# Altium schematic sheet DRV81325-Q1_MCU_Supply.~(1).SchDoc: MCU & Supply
size 431 x 279 mm; Date: Not shown in title block; ApprovedBy: Not shown in title block; CheckedBy: Not shown in title block; Author: Not shown in title block; CompanyName: Not shown in title block; DrawnBy: Mojtaba Afshar; Engineer: Not shown in title block; Organization: Not shown in title block; Address1: Not shown in title block; Address2: Not shown in title block; Address3: Not shown in title block; Address4: Not shown in title block; DocumentNumber: 2; Revision: Use project parameter SCH_Rev; SheetNumber: 1; SheetTotal: 5; PageSetup: Record=PageOptions¦CenterHorizontal=True¦CenterVertical=True¦PrintScale=1.00¦XCorrection=1.00¦YCorrection=1.00¦PrintKind=0¦BorderSize=5000000¦LeftOffset=0¦BottomOffset=0¦Orientation=2¦PaperLength=1000¦PaperWidth=1000¦Scale=100¦PaperSource=15¦PrintQuality=600¦MediaType=1¦DitherType=10¦PaperKind=Letter¦PrintScaleMode=1
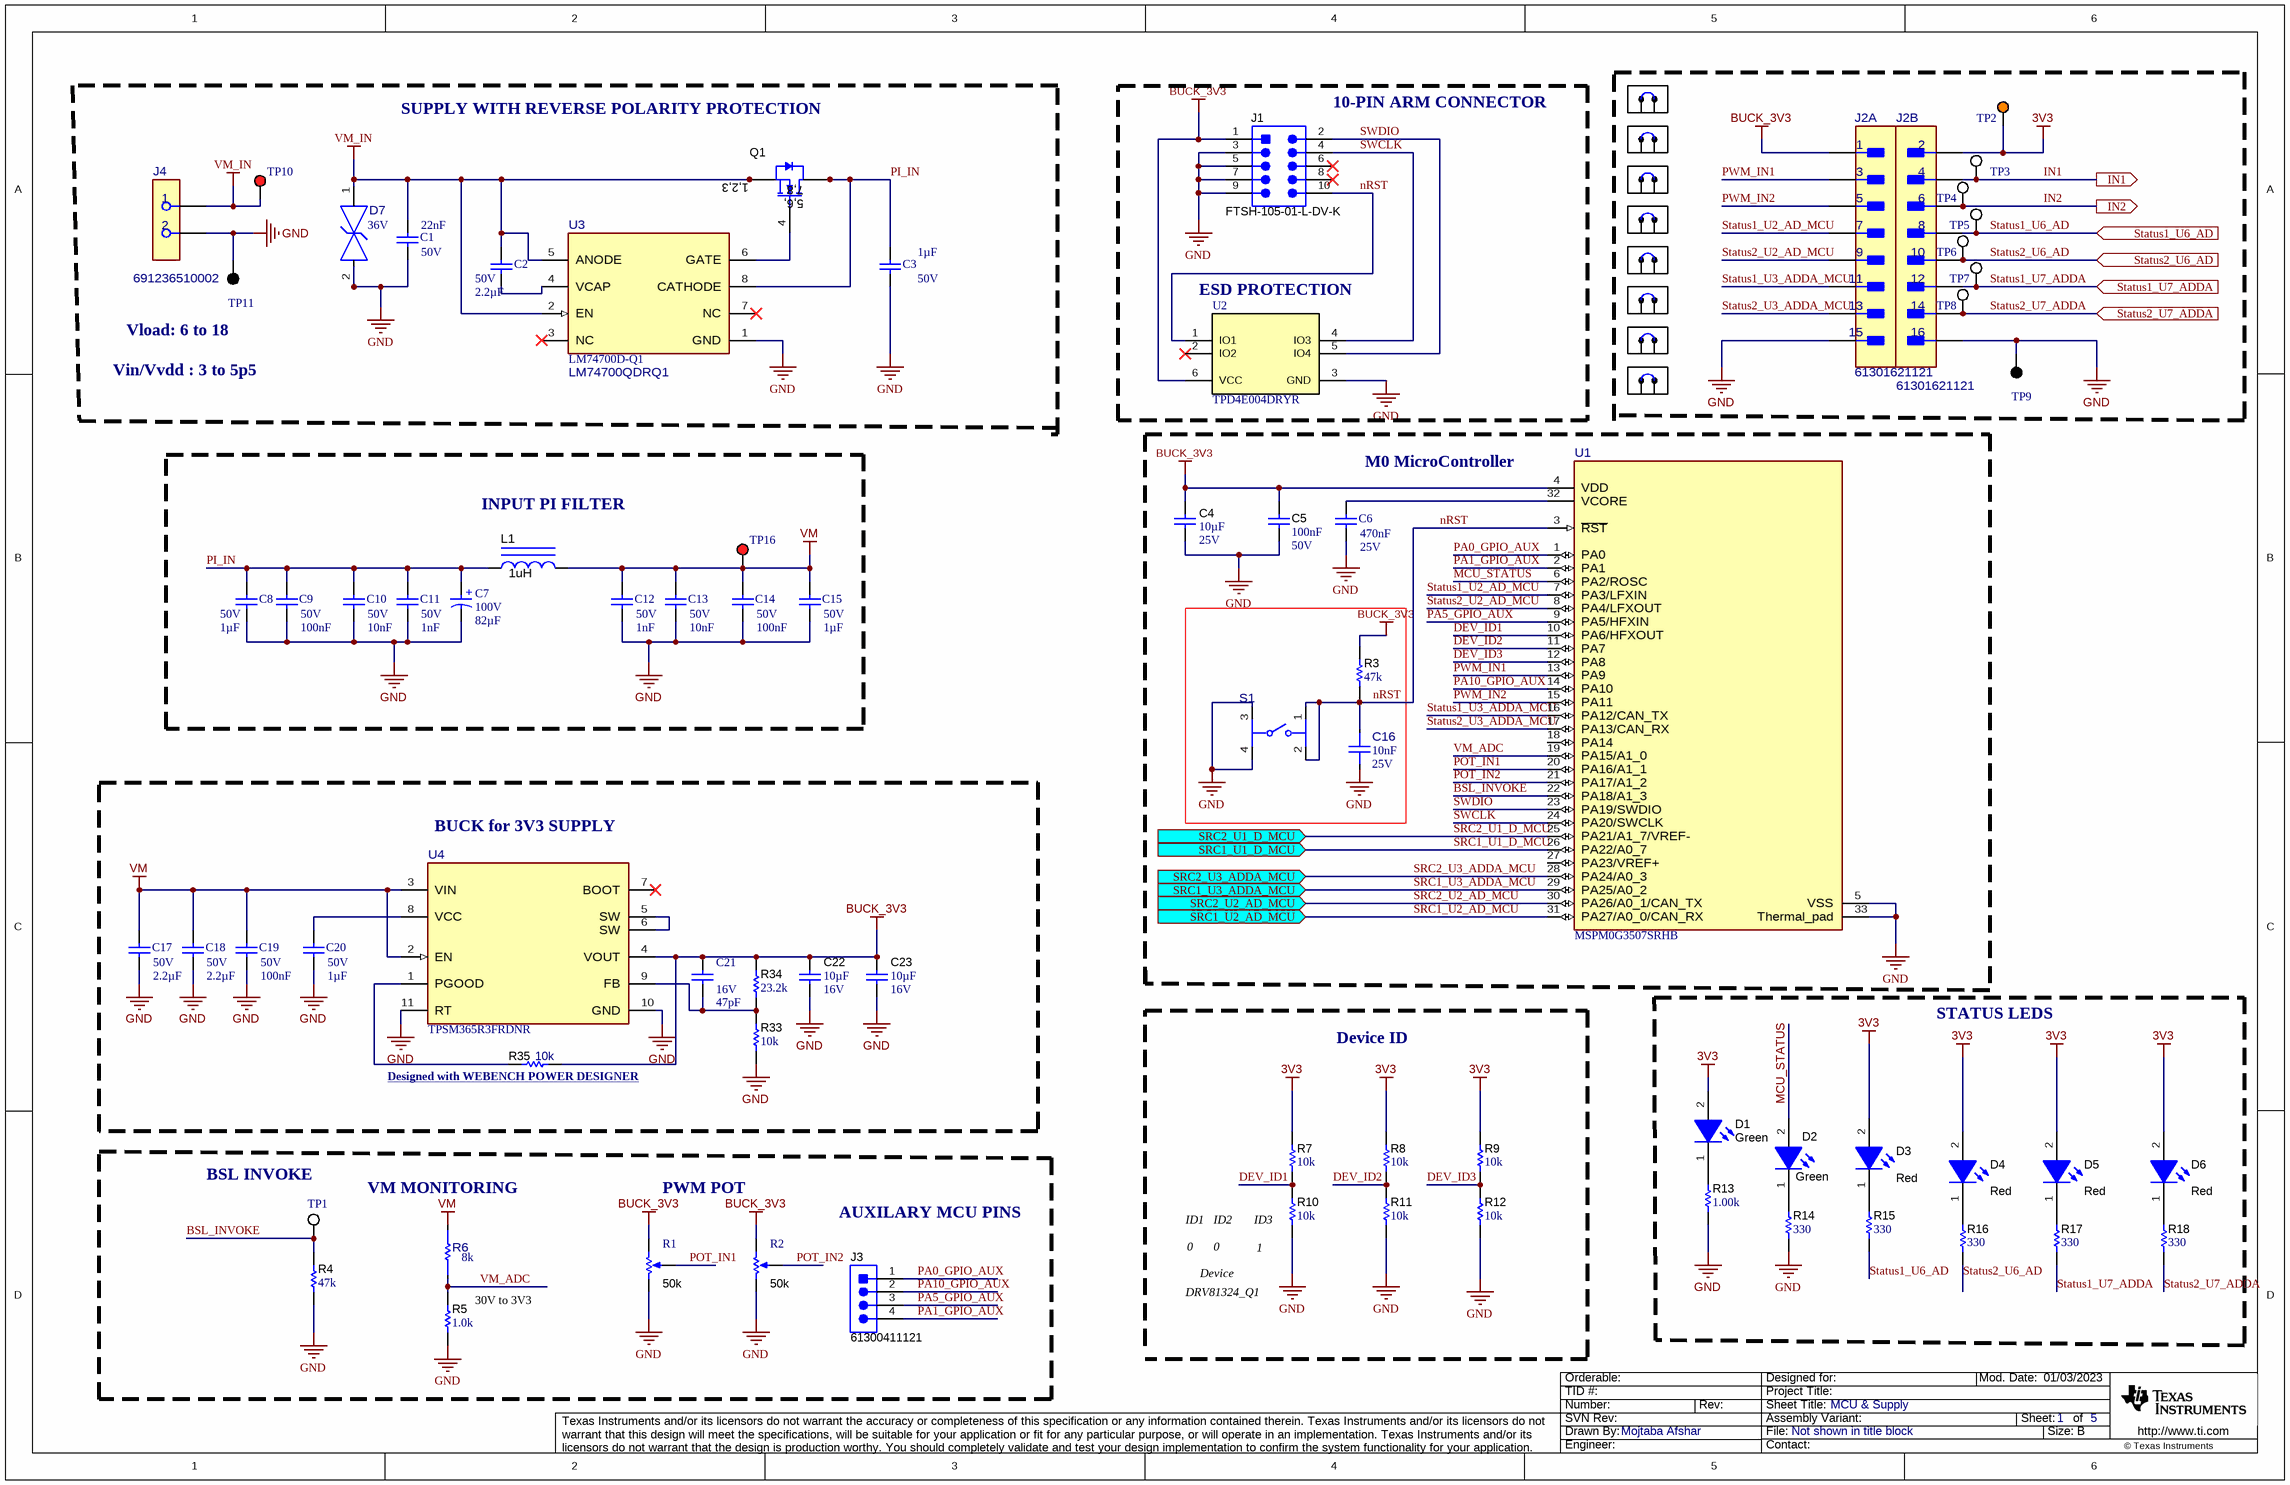
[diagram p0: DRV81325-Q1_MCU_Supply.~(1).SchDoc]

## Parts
C1  Cap_F: 22nF  Rated Voltage (DC): 50V  [WCAP-CSGP_0603_L1.6W0.8H0.8_Reflow]  (hidden comment: 885012206091)
C2  Cap_F: 2.2µF  Rated Voltage (DC): 50V  [WCAP-CSGP_1812_L4.5W3.2H2.5]  (hidden comment: 885012210032)
C3  Cap_F: 1µF  Rated Voltage (DC): 50V  [WCAP-CSGP_1206_L3.2W1.6H1.6]  (hidden comment: 885012208093)
C4  Cap_F: 10µF  VDC_V: 25V  [0603]  (hidden comment: GRM188R61E106KA73D)
C5  Cap_F: 100nF  VDC_V: 50V  [0603]  (hidden comment: 885012206095)
C6  value 470nF  Rated Voltage (DC): 25V  [WCAP-CSGP_0603_L1.6W0.8H0.8_Reflow]  (hidden comment: 885012206075R)
C7  Cap_F: 82µF  Rated Voltage (DC): 100V  [WCAP-ATUL_D10H20]  (hidden comment: 860040875004)
C8  Cap_F: 1µF  Rated Voltage (DC): 50V  [WCAP-CSGP_1206_L3.2W1.6H1.6]  (hidden comment: 885012208093)
C9  Cap_F: 100nF  Rated Voltage (DC): 50V  [WCAP-CSGP_0603_L1.6W0.8H0.8_Reflow]  (hidden comment: 885012206095)
C10  Cap_F: 10nF  Rated Voltage (DC): 50V  [WCAP-CSGP_0402_L1W0.5H0.5]  (hidden comment: 885012205067)
C11  Cap_F: 1nF  Rated Voltage (DC): 50V  [WCAP-CSGP_0402_L1W0.5H0.5]  (hidden comment: 885012205061)
C12  Cap_F: 1nF  Rated Voltage (DC): 50V  [WCAP-CSGP_0402_L1W0.5H0.5]  (hidden comment: 885012205061)
C13  Cap_F: 10nF  Rated Voltage (DC): 50V  [WCAP-CSGP_0402_L1W0.5H0.5]  (hidden comment: 885012205067)
C14  Cap_F: 100nF  Rated Voltage (DC): 50V  [WCAP-CSGP_0603_L1.6W0.8H0.8_Reflow]  (hidden comment: 885012206095)
C15  Cap_F: 1µF  Rated Voltage (DC): 50V  [WCAP-CSGP_1206_L3.2W1.6H1.6]  (hidden comment: 885012208093)
C16  Cap_F: 10nF  VDC_V: 25V  [FP-885012206065_0603-MFG]  (hidden comment: 885012206065)
C17  Cap_F: 2.2µF  Rated Voltage (DC): 50V  [WCAP-CSGP_1812_L4.5W3.2H2.5]  (hidden comment: 885012210032)
C18  Cap_F: 2.2µF  Rated Voltage (DC): 50V  [WCAP-CSGP_1812_L4.5W3.2H2.5]  (hidden comment: 885012210032)
C19  Cap_F: 100nF  Rated Voltage (DC): 50V  [WCAP-CSGP_0603_L1.6W0.8H0.8_Reflow]  (hidden comment: 885012206095)
C20  Cap_F: 1µF  Rated Voltage (DC): 50V  [WCAP-CSGP_1206_L3.2W1.6H1.6]  (hidden comment: 885012208093)
C21  Rated Voltage (DC): 16V  Cap_F: 47pF  [WCAP-CSGP_0402_L1W0.5H0.5]  (hidden comment: 885012005029)
C22  VDC_V: 16V  ValueDisplayed: 10µF  [0805_150]  (hidden comment: 885012107014)
C23  VDC_V: 16V  ValueDisplayed: 10µF  [0805_150]  (hidden comment: 885012107014)
D1  value Green  [WL-SMCW_GREEN]  (hidden comment: 150060VS75000)
D2  value Green  [WL-SMCW_GREEN]  (hidden comment: 150060VS75000)
D3  value Red  [WL-SMCW_RED]  (hidden comment: 150060RS75000)
D4  value Red  [WL-SMCW_RED]  (hidden comment: 150060RS75000)
D5  value Red  [WL-SMCW_RED]  (hidden comment: 150060RS75000)
D6  value Red  [WL-SMCW_RED]  (hidden comment: 150060RS75000)
D7  VRWM: 36V  [FP-SMBJ36CA-13-F_SMB-MFG]  (hidden comment: SMBJ36CA-13-F)
J1  FTSH-105-01-L-DV-K  [Samtec_FTSH-105-01-x-DV-K]
J2  61301621121  [FP-61301621121_HDR16-MFG]  (parts A,B of 2)
J3  61300411121  [WURTH_61300411121]
J4  691236510002  [FP-691236510002_HHR2-MFG]
L1  ValueDisplayed: 1uH  [WE-HCC_1210]  (hidden comment: 7443320100)
Q1  CSD19502Q5B  [DNK0008A]  (value not drawn)
R1  value 50k  [Bourns_3352T]  (hidden comment: 3352T-1-503LF)
R2  value 50k  [Bourns_3352T]  (hidden comment: 3352T-1-503LF)
R3  ValueDisplayed: 47k  [0402]  (hidden comment: CRCW040247K0JNED)
R4  ValueDisplayed: 47k  [0402]  (hidden comment: CRCW040247K0JNED)
R5  ValueDisplayed: 1.0k  [0603]  (hidden comment: RC0603JR-071KL)
R6  value 8k  [FP-RT0603BRE078KL_0603-MFG]  (hidden comment: RT0603BRE078KL)
R7  ValueDisplayed: 10k  [0603L]  (hidden comment: RC0603JR-0710KL)
R8  ValueDisplayed: 10k  [0603L]  (hidden comment: RC0603JR-0710KL)
R9  ValueDisplayed: 10k  [0603L]  (hidden comment: RC0603JR-0710KL)
R10  ValueDisplayed: 10k  [0603L]  (hidden comment: RC0603JR-0710KL)
R11  ValueDisplayed: 10k  [0603L]  (hidden comment: RC0603JR-0710KL)
R12  ValueDisplayed: 10k  [0603L]  (hidden comment: RC0603JR-0710KL)
R13  ValueDisplayed: 1.00k  [0603]  (hidden comment: RC0603FR-071KL)
R14  ValueDisplayed: 330  [0603]  (hidden comment: RC0603JR-07330RL)
R15  ValueDisplayed: 330  [0603]  (hidden comment: RC0603JR-07330RL)
R16  ValueDisplayed: 330  [0603]  (hidden comment: RC0603JR-07330RL)
R17  ValueDisplayed: 330  [0603]  (hidden comment: RC0603JR-07330RL)
R18  ValueDisplayed: 330  [0603]  (hidden comment: RC0603JR-07330RL)
R33  ValueDisplayed: 10k  [0603L]  (hidden comment: RC0603JR-0710KL)
R34  ValueDisplayed: 23.2k  [0603]  (hidden comment: RC0603FR-0723K2L)
R35  ValueDisplayed: 10k  [0603L]  (hidden comment: RC0603JR-0710KL)
S1  430481025816  [FP-430481025816_SMT_SW_6MM2_6MM2-MFG]  (value not drawn)
SH1-J2-1  60900213421  [Wurth_60900213421]  (value not drawn)
SH2-J2  60900213421  [Wurth_60900213421]  (value not drawn)
SH3-J2  60900213421  [Wurth_60900213421]  (value not drawn)
SH4-J2  60900213421  [Wurth_60900213421]  (value not drawn)
SH5-J2  60900213421  [Wurth_60900213421]  (value not drawn)
SH6-J2  60900213421  [Wurth_60900213421]  (value not drawn)
SH7-J2  60900213421  [Wurth_60900213421]  (value not drawn)
SH8-J2  60900213421  [Wurth_60900213421]  (value not drawn)
TP1  5002  [Keystone5002]  (value not drawn)
TP2  5013  [Keystone5013]  (value not drawn)
TP3  5012  [Keystone5012]  (value not drawn)
TP4  5012  [Keystone5012]  (value not drawn)
TP5  5012  [Keystone5012]  (value not drawn)
TP6  5012  [Keystone5012]  (value not drawn)
TP7  5012  [Keystone5012]  (value not drawn)
TP8  5012  [Keystone5012]  (value not drawn)
TP9  5011  [Keystone5011]  (value not drawn)
TP10  5010  [Keystone5010]  (value not drawn)
TP11  5011  [Keystone5011]  (value not drawn)
TP16  5010  [Keystone5010]  (value not drawn)
U1  MSPM0G3507SRHB  [RHB0032E-MFG]
U2  TPD4E004DRYR  [DRY0006A]
U3  LM74700QDRQ1  PartNumber: LM74700D-Q1  [D0008A-MFG]
U4  TPSM365R3FRDNR  [RDN0011A-MFG]

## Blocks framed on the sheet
INPUT PI FILTER: C7-C15 L1 TP16
BUCK for 3V3 SUPPLY: C17-C23 R33-R35 U4
STATUS LEDS: D1-D6 R13-R18

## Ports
IN1 (out), IN2 (out), SRC1_U1_D_MCU (in), SRC1_U2_AD_MCU (in), SRC1_U3_ADDA_MCU (in), SRC2_U1_D_MCU (in), SRC2_U2_AD_MCU (in), SRC2_U3_ADDA_MCU (in), Status1_U6_AD (in), Status1_U7_ADDA (in), Status2_U6_AD (in), Status2_U7_ADDA (in)

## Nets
3V3: D1.2(A) D3.2(A) D4.2(A) D5.2(A) D6.2(A) J2.2 R7.1 R8.1 R9.1 TP2.1
BUCK_3V3: C4.1 C5.1 C21.2 C22.1 C23.1 J1.1 J2.1 R1.1(CCW) R2.1(CCW) R3.2 R34.2 R35.2 U1.4(VDD) U2.6(VCC) U4.4(VOUT)
GND: C1.1 C3.1 C4.2 C5.2 C6.1 C7.2(N) C8.1 C9.1 C10.1 C11.1 C12.1 C13.1 C14.1 C15.1 C16.2 C17.1 C18.1 C19.1 C20.1 C22.2 C23.2 D7.2 J1.3 J1.5 J1.7 J1.9 J2.15 J2.16 J4.2 R1.3(CW) R2.3(CW) R4.1 R5.1 R10.2 R11.2 R12.2 R13.1 R14.1 R33.1 S1.3 S1.4 TP9.1 TP11.1 U1.5(VSS) U1.33(Thermal_pad) U2.3(GND) U3.1(GND) U4.10(GND) U4.11(RT)
VM: C12.2 C13.2 C14.2 C15.2 C17.2 C18.2 C19.2 L1.2 R6.2 TP16.1 U4.2(EN) U4.3(VIN)
VM_IN: C1.2 C2.2 D7.1 J4.1 Q1.1(S) Q1.2(S) Q1.3(S) TP10.1 U3.2(EN) U3.5(ANODE)
BSL_INVOKE: R4.2 TP1.1 U1.22(PA18/A1_3)
DEV_ID1: R7.2 R10.1 U1.10(PA6/HFXOUT)
DEV_ID2: R8.2 R11.1 U1.11(PA7)
DEV_ID3: R9.2 R12.1 U1.12(PA8)
IN1: J2.4 TP3.1 ; port IN1
IN2: J2.6 TP4.1 ; port IN2
MCU_STATUS: D2.2(A) U1.6(PA2/ROSC)
nRST: C16.1 J1.10 R3.1 S1.1 S1.2 U1.3(~{RST}) U2.1(IO1)
PA0_GPIO_AUX: J3.1 U1.1(PA0)
PA1_GPIO_AUX: J3.4 U1.2(PA1)
PA5_GPIO_AUX: J3.3 U1.9(PA5/HFXIN)
PA10_GPIO_AUX: J3.2 U1.14(PA10)
PI_IN: C3.2 C7.1(P) C8.2 C9.2 C10.2 C11.2 L1.1 Q1.5(D) Q1.6(D) Q1.7(D) Q1.8(D) Q1.9(D) U3.8(CATHODE)
POT_IN1: R1.2(WIPER) U1.20(PA16/A1_1)
POT_IN2: R2.2(WIPER) U1.21(PA17/A1_2)
PWM_IN1: J2.3 U1.13(PA9)
PWM_IN2: J2.5 U1.15(PA11)
SRC1_U1_D_MCU: U1.26(PA22/A0_7) ; port SRC1_U1_D_MCU
SRC1_U2_AD_MCU: U1.31(PA27/A0_0/CAN_RX) ; port SRC1_U2_AD_MCU
SRC1_U3_ADDA_MCU: U1.29(PA25/A0_2) ; port SRC1_U3_ADDA_MCU
SRC2_U1_D_MCU: U1.25(PA21/A1_7/VREF-) ; port SRC2_U1_D_MCU
SRC2_U2_AD_MCU: U1.30(PA26/A0_1/CAN_TX) ; port SRC2_U2_AD_MCU
SRC2_U3_ADDA_MCU: U1.28(PA24/A0_3) ; port SRC2_U3_ADDA_MCU
Status1_U2_AD_MCU: J2.7 U1.7(PA3/LFXIN)
Status1_U3_ADDA_MCU: J2.11 U1.16(PA12/CAN_TX)
Status1_U6_AD: J2.8 R15.1 TP5.1 ; port Status1_U6_AD
Status1_U7_ADDA: J2.12 R17.1 TP7.1 ; port Status1_U7_ADDA
Status2_U2_AD_MCU: J2.9 U1.8(PA4/LFXOUT)
Status2_U3_ADDA_MCU: J2.13 U1.17(PA13/CAN_RX)
Status2_U6_AD: J2.10 R16.1 TP6.1 ; port Status2_U6_AD
Status2_U7_ADDA: J2.14 R18.1 TP8.1 ; port Status2_U7_ADDA
SWCLK: J1.4 U1.24(PA20/SWCLK) U2.4(IO3)
SWDIO: J1.2 U1.23(PA19/SWDIO) U2.5(IO4)
VM_ADC: R5.2 R6.1 U1.19(PA15/A1_0)
NetC2_1: C2.1 U3.4(VCAP)
NetC6_2: C6.2 U1.32(VCORE)
NetC20_2: C20.2 U4.8(VCC)
NetC21_1: C21.1 R33.2 R34.1 U4.9(FB)
NetD1_1: D1.1(K) R13.2
NetD2_1: D2.1(K) R14.2
NetD3_1: D3.1(K) R15.2
NetD4_1: D4.1(K) R16.2
NetD5_1: D5.1(K) R17.2
NetD6_1: D6.1(K) R18.2
NetQ1_4: Q1.4(G) U3.6(GATE)
NetR35_1: R35.1 U4.1(PGOOD)
NetU4_5: U4.5(SW) U4.6(SW)

Not connected (* = marked no-connect by the designer): J1 6* 8*; U1 18(PA14) 27(PA23/VREF+); U2 2(IO2)*; U3 3(NC)* 7(NC)*; U4 7(BOOT)*

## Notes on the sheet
- SUPPLY WITH REVERSE POLARITY PROTECTION
- (near J1) 10-PIN ARM CONNECTOR
- (near U2) ESD PROTECTION
- (near TP11) Vload: 6 to 18
- Vin/Vvdd : 3 to 5p5
- M0 MicroController
- Device ID
- (near R35) Designed with WEBENCH POWER DESIGNER <https://webench.ti.com/power-designer/switching-regulator/customize/4?VinMin=4.5&VinMax=65&O1V=3.3&O1I=0.3&base_pn=TPSM365R3F&AppType=None&Flavor=None&op_TA=30&origin=pf_panel&lang_chosen=en-US&optfactor=3&Topology=Buck&flavor=None&VoltageOption=None>
- (near TP1) BSL INVOKE
- (near R6) VM MONITORING
- PWM POT
- AUXILARY MCU PINS
- ID1
- ID2
- (near R10) ID3
- 30V to 3V3
- DRV81324_Q1
- 0
- Device
- (near R10) 1

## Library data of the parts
C1 = CMP-0119398-1: WCAP-CSGP Multilayer Ceramic Chip Capacitor, General Purpose, size 0603, X7R, 22nF, 50VDC; Manufacturer: Wurth Elektronik; Capacitance Tolerance: +/-10%; Case/Size Code: 0603; Dissipation Factor: 2.5%; Insulation Resistance: 10GOhm; Technical Reference: X7R0603223K050DFCT10000
C2 C17 C18 = CMP-0119739-1: WCAP-CSGP Multilayer Ceramic Chip Capacitor, General Purpose, size 1812, X7R, 2.2µF, 50VDC; Manufacturer: Wurth Elektronik; Capacitance Tolerance: +/-10%; Case/Size Code: 1812; Dissipation Factor: 2.5%; Insulation Resistance: 0.2GOhm; Technical Reference: X7R1812225K050DFCT10000
C3 C8 C15 C20 = CMP-0119636-1: WCAP-CSGP Multilayer Ceramic Chip Capacitor, General Purpose, size 1206, X7R, 1µF, 50VDC; Manufacturer: Wurth Elektronik; Capacitance Tolerance: +/-10%; Case/Size Code: 1206; Dissipation Factor: 3%; Insulation Resistance: 0.5GOhm; Technical Reference: X7R1206105K050DFCT10000
C4 = CMP-0860569-1: CAP, CERM, 10 µF, 25 V,+/- 10%, X5R, 0603; Manufacturer: MuRata; TaMin_C: -55°C; Polarized: N; SizeAreaWB_mm2: 4.68; U/M: EA; Value: 10uF; TaMax_C: 85°C; SizeZ_mm: 1; SizeX_mm: 1.6; SizeY_mm: 0.8; SizeArea_mm2: 1.28; AEC Category: Q200
C5 = CMP-0006837-4: CAP, CERM, 0.1 uF, 50 V, +/- 10%, X7R, 0603; Manufacturer: Wurth Elektronik; TaMin_C: -55°C; Polarized: N; SizeAreaWB_mm2: 4.68; Value1: Unknown; U/M: EA; Value: 0.1uF; TaMax_C: 125°C; SizeZ_mm: 1; SizeX_mm: 1.6; SizeY_mm: 0.8; SizeArea_mm2: 1.28; AEC Category: Q200
C6 = CMP-0119380-1: WCAP-CSGP Multilayer Ceramic Chip Capacitor, General Purpose, size 0603, X7R Class II, 470nF, 25VDC; Manufacturer: Wurth Elektronik; Capacitance Tolerance: +/-10%; Case/Size Code: 0603; Dissipation Factor: 10%; Insulation Resistance: 1.1GOhm; Technical Reference: X7R0603474K025DFCT20000
C7 = CMP-0102582-1: WCAP-ATUL Aluminum Electrolytic Capacitor, Radial, THT, D10 x H20mm, 82µF, 100V; Manufacturer: Wurth Elektronik; Capacitance Tolerance: 20%; Dissipation Factor: 9%; Endurance: 7000h; Leakage Current: 82uA; Ripple Current: 600mA; Technical Reference: ATDF200820M100DSPAAG000
C9 C14 C19 = CMP-0119402-1: WCAP-CSGP Multilayer Ceramic Chip Capacitor, General Purpose, size 0603, X7R, 100nF, 50VDC; Manufacturer: Wurth Elektronik; Capacitance Tolerance: +/-10%; Case/Size Code: 0603; Dissipation Factor: 3%; Insulation Resistance: 5GOhm; Technical Reference: X7R0603104K050DFCT10000
C10 C13 = CMP-0119297-1: WCAP-CSGP Multilayer Ceramic Chip Capacitor, General Purpose, size 0402, X7R, 10nF, 50VDC; Manufacturer: Wurth Elektronik; Capacitance Tolerance: +/-10%; Case/Size Code: 0402; Dissipation Factor: 2.5%; Insulation Resistance: 10GOhm; Technical Reference: X7R0402103K050DFCT10000
C11 C12 = CMP-0119291-1: WCAP-CSGP Multilayer Ceramic Chip Capacitor, General Purpose, size 0402, X7R, 1nF, 50VDC; Manufacturer: Wurth Elektronik; Capacitance Tolerance: +/-10%; Case/Size Code: 0402; Dissipation Factor: 2.5%; Insulation Resistance: 10GOhm; Technical Reference: X7R0402102K050DFCT10000
C16 = CMP-0120893-1: 10000 pF ±10% 25V Ceramic Capacitor X7R 0603 (1608 Metric); Manufacturer: Wurth Electronics; AEC Qualified: No; SizeZ_mm: 0.87mm; TempCo: 15%; Value: 10nF
C21 = CMP-0050226-1: WCAP-CSGP Multilayer Ceramic Chip Capacitor, General Purpose, size 0402, NP0, 47pF, 16VDC; Manufacturer: Wurth Elektronik; Capacitance Tolerance: +/-5%; Insulation Resistance: 10GOhm; Q Factor: 1000; Technical Reference: NP00402470J016DFCT10000; Case/Size Code: 0402
C22 C23 = CMP-0078154-1: CAP, CERM, 10 µF, 16 V,+/- 20%, X5R, 0805; Manufacturer: Wurth Elektronik; TaMin_C: -55°C; Polarized: N; SizeAreaWB_mm2: 6.75; U/M: EA; Value: 10uF; TaMax_C: 85°C; SizeZ_mm: 1.5; SizeX_mm: 2; SizeY_mm: 1.25; Cap_Case: 0805; SizeArea_mm2: 2.5; AEC Category: Q200
D1 D2 = CMP-0002894-2: LED, Green, SMD; Manufacturer: Wurth Elektronik; Type: AlInGaP; Value2: 2V; Io_A: 20mA; Value1: W
D3-D6 = CMP-0002947-3: LED, Red, SMD; Manufacturer: Wurth Elektronik; Value1: 0.072W; Vf_V: 2V; Angle: 140; Tjmax_C: 85°C; Type: AlInGaP; Vr_V: 5V; Io_A: 30mA; Power_TotalModule: 72mW
D7 = CMP-0098087-1: 58.1V Clamp 10.3A Ipp Tvs Diode Surface Mount SMB; Manufacturer: Diodes Inc; AEC Qualified: No; Standoff Height: 0.05mm; TJmax_C: +150°C; Direction: Bidirectional; Breakdown Voltage: 40V; SizeZ_mm: 2.5mm; Ppk: 600W; Number Of Channels: 1
J1 = CMP-0075634-2: Header(Shrouded), 1.27mm, 5x2, Gold, SMT; Manufacturer: Samtec; Pitch_mm: 1.27; Gender: Male; Cert_CSA: Y; Current_A: 3.3A; Row_Count: 2
J2 = CMP-0125672-1: Connector Header Through Hole 16 position 0.100" (2.54mm); Manufacturer: Wurth; ContactFinish: Gold; Current_A: 3A; Row_Count: 2; Voltage_V: 250V; AEC Qualified: No; Conn Gender: Male; Conn Orientation: Straight; SizeZ_mm: 8.89mm
J3 = CMP-0054798-2: Header, 2.54 mm, 4x1, Gold, TH; Manufacturer: Wurth Elektronik; Pitch_mm: 2.54; Gender: Male; Row_Count: 1; Cert_UL: Y; Shrouded: N
J4 = CMP-0121282-1: 2 Position Wire to Board Terminal Block Horizontal with Board 0.200" (5.08mm) Through Hole; Manufacturer: Wurth Electronics; Current_A: 20A; Row_Count: 1; Voltage_V: 300V; AEC Qualified: No; Conn Gender: Female; Is Female: yes; Max Wire Gauge: 12; Min Wire Gauge: 30; SizeZ_mm: 18.1mm
L1 = CMP-0063986-1: Inductor, Shielded Drum Core, Ferrite, 1 uH, 24 A, 0.0012 ohm, SMD; Manufacturer: Wurth Elektronik; Isat: 32A @ 30% inductance drop; Irms: 24A @ 50C rise; Green_Lifecycle: Active; SizeAreaWB_mm2: 188.94; DCR_ohm: 1.2m; Green_REACh: Passed; Value: 1uH; Imax_A: 24A; SizeZ_mm: 10; SizeX_mm: 12.1; SizeY_mm: 11.4; SizeArea_mm2: 137.94; Ind_H: 1µH; AEC Category: Q200
Q1 = CMP-0000915-2: MOSFET, N-CH, 80 V, 100 A, DNK0008A (VSON-CLIP-8); Alternate Manufacturer: None; Manufacturer: Texas Instruments; SizeZ_mm: 1; ChType: N; Value2: 48 nC; VdsMax_V: 80V; SizeX_mm: 6; SizeY_mm: 5; Vgs_V: 20V; Value: 80V; SizeArea_mm2: 30; AEC Category: Q101; IdsMax_A: 100A; SizeAreaWB_mm2: 56; U/M: EA; QgTyp_nC: 48
R1 R2 = CMP-0001777-2: Trimming Potentiometer, 50K, 0.5W, TH; Manufacturer: Bourns; CompType: Trimmer
R3 R4 = CMP-0026935-3: RES, 47 k, 5%, 0.063 W, AEC-Q200 Grade 0, 0402; Manufacturer: Vishay-Dale; Power_W: 63mW; TempCo: 200 ppm/C; Value_Code: 47k0; Value: 47k; EIA_Code: E24; SizeX_mm: 1; SizeY_mm: 0.5; SizeZ_mm: 0.6; Value2: 0.063W; AEC Qualified: Y; VDC_V: 50V; AEC Category: Q200; AEC Grade: 0
R5 = CMP-0025899-5: RES, 1.0 k, 5%, 0.1 W, 0603; Manufacturer: Yageo; Power_W: 100mW; TempCo: 100 ppm/C; Value_Code: 1k00; Value: 1.0k; EIA_Code: E24; Res_ohm: 1k; SizeX_mm: 1.6; SizeY_mm: 0.8; SizeZ_mm: 1; Value2: 0.1W; SizeArea_mm2: 1.28; AEC Qualified: N; VDC_V: 75V; AEC Category: Q200; SizeAreaWB_mm2: 4.68
R6 = CMP-0122747-1: 8 kOhms ±0.1% 0.1W, 1/10W Chip Resistor 0603 (1608 Metric) Thin Film; Manufacturer: Yageo; AEC Qualified: No; Power_W: 100mW; SizeZ_mm: 0.55mm; TempCo: 50ppm/°C; VDC_V: 75V
R7-R12 R33 = CMP-0025886-5: RES, 10 k, 5%, 0.1 W, 0603; Manufacturer: Yageo; Power_W: 100mW; TempCo: 100 ppm/C; Value_Code: 10k0; Value: 10k; EIA_Code: E24; SizeX_mm: 1.6; SizeY_mm: 0.8; SizeZ_mm: 1; Value2: 0.1W; SizeArea_mm2: 1.28; AEC Qualified: N; VDC_V: 75V; AEC Category: Q200; SizeAreaWB_mm2: 4.68
R13 = CMP-0022895-5: RES, 1.00 k, 1%, 0.1 W, 0603; Manufacturer: Yageo; Power_W: 100mW; TempCo: 100 ppm/C; Value_Code: 1k00; Value: 1.00k; EIA_Code: E96; Res_ohm: 1k; SizeX_mm: 1.6; SizeY_mm: 0.8; SizeZ_mm: 1; Value2: 0.1W; SizeArea_mm2: 1.28; AEC Qualified: N; VDC_V: 75V; AEC Category: Q200; SizeAreaWB_mm2: 4.68
R14-R18 = CMP-0025912-5: RES, 330, 5%, 0.1 W, 0603; Manufacturer: Yageo; Power_W: 100mW; TempCo: 100 ppm/C; Value_Code: 330R; Value: 330; EIA_Code: E24; SizeX_mm: 1.6; SizeY_mm: 0.8; SizeZ_mm: 1; Value2: 0.1W; SizeArea_mm2: 1.28; AEC Qualified: N; VDC_V: 75V; AEC Category: Q200; SizeAreaWB_mm2: 4.68
R34 = CMP-0022933-5: RES, 23.2 k, 1%, 0.1 W, 0603; Manufacturer: Yageo; Power_W: 100mW; TempCo: 100 ppm/C; Value_Code: 23k2; Value: 23.2k; EIA_Code: E96; SizeX_mm: 1.6; SizeY_mm: 0.8; SizeZ_mm: 1; Value2: 0.1W; SizeArea_mm2: 1.28; AEC Qualified: N; VDC_V: 75V; AEC Category: Q200; SizeAreaWB_mm2: 4.68
R35 = CMP-0025886-3: RES, 10 k, 5%, 0.1 W, 0603; Manufacturer: Yageo; Power_W: 100mW; TempCo: 100 ppm/C; Value_Code: 10k0; U/M: EA; Value: 10k; EIA_Code: E24; SizeX_mm: 1.6; SizeY_mm: 0.8; SizeZ_mm: 1; Value2: 0.1W; SizeArea_mm2: 1.28; VDC_V: 50V; AEC Category: Q200
S1 = CMP-0097347-1: Tactile Switch SPST-NO Top Actuated Surface Mount; Manufacturer: Wurth Electronics; VDC_V: 12V; Electromechanical Life: 1000000Cycles; SizeZ_mm: 2.7mm; Coil Resistance_ohm: 100mΩ; Operating Force: 160gf; AEC Qualified: No; Contact Current Rating: 50mA
SH1-J2-1 SH2-J2 SH3-J2 SH4-J2 SH5-J2 SH6-J2 SH7-J2 SH8-J2 = CMP-0003761-2: Shunt, 2.54mm, Gold, Black; Manufacturer: Wurth Elektronik
TP1 = CMP-0055139-2: Test Point, Miniature, White, TH; Manufacturer: Keystone Electronics; ContactFinish: Silver; Green_REACh: Passed; CT: TRUE; Green_Lifecycle: Active; CNHeader: FALSE
TP2 = CMP-0055150-1: Test Point, Multipurpose, Orange, TH; Manufacturer: Keystone; CNHeader: FALSE; Green_Lifecycle: Active; Green_REACh: Passed; ContactFinish: Silver; CT: TRUE
TP3-TP8 = CMP-0055149-2: Test Point, Multipurpose, White, TH; Manufacturer: Keystone Electronics; ContactFinish: Silver; CT: TRUE; CNHeader: FALSE; Green_Lifecycle: Active; Green_REACh: Passed
TP9 = CMP-0055148-2: Test Point, Multipurpose, Black, TH; Manufacturer: Keystone Electronics; CNHeader: FALSE; ContactFinish: Silver; Green_REACh: Passed; Green_Lifecycle: Active; CT: TRUE
TP10 TP16 = CMP-0055147-2: Test Point, Multipurpose, Red, TH; Manufacturer: Keystone Electronics; CNHeader: FALSE; Green_Lifecycle: Active; Green_REACh: Passed; ContactFinish: Silver; CT: TRUE
TP11 = CMP-0055148-2: Test Point, Multipurpose, Black, TH; Manufacturer: Keystone Electronics; CNHeader: FALSE; Green_Lifecycle: Active; Green_REACh: Passed; ContactFinish: Silver; CT: TRUE
U1 = CMP-0093963-1: Mixed-Signal Microcontrollers with CAN-FD Interface, VQFN32; Manufacturer: Texas Instruments; TaMin_C: -40°C; Interface: I2C,SPI,UART,CAN,LIN,IrDA,SMBus; Number Of Cores: 1; Number Of Pwm Channels: 16; Data Bus Width: 32bits; Frequency_Fixed: 80MHz; Core Architecture: ARM Cortex-M0+; Number Of Timers/Counters: 7; Number Of Adc Channels: 10; Number Of Uart Channels: 4; Standoff Height: 0mm; Ram Size: 32KBytes; Number Of A/D Converters: 2; SizeZ_mm: 1mm; AEC Qualified: No; TaMax_C: +125°C; Memory Size: 128KBytes; TJmax_C: +130°C; Min Supply Voltage: 1.62V; Max Supply Voltage: 3.6V; Memory Type: FLASH; Number Of I/Os: 28
U2 = CMP-0043115-2: ESD-Protection Array for High-Speed Data Interfaces, 4 Channels, -40 to +85 degC, 6-pin SON (DRY), Green (RoHS & no Sb/Br); Manufacturer: Texas Instruments; IO Leakage Current(nA): 1; USB High Speed: TRUE; IO Capacitance(Typ)(pF): 1.6; SubFamily: ESD Solution; IEC 61000-4-2 Contact(+/- kV): 8; Breakdown Voltage(Min)(V): 6; IEC 61000-4-2 Air-Gap(+/- kV): 12; AEC Category: Q200; AEC Qualified: N; CompType: IC; SizeAreaWB_mm2: 4.9; SizeArea_mm2: 1.45; SizeX_mm: 1.0; SizeZ_mm: 0.6
U3 = CMP-0125797-1: Manufacturer: Texas Instruments; SizeZ_mm: 1.75mm; Standoff Height: 0.11mm
U4 = CMP-0094617-1: 3-V to 65-V Input, 1-V to 13-V Output, 600-mA Synchronous Buck Converter Power Module in a HotRod QFN Package; Manufacturer: Texas Instruments; SizeZ_mm: 2.1mm; AEC Qualified: No; Max Duty Cycle: 98%; Max Supply Voltage: 65V; Min Supply Voltage: 3.6V; Nominal Supply Current: 17-18uA; Number Of Outputs: 1; Output Type: AdjustableProgrammable; Output Voltage: 1-13V; Standoff Height: 0mm; Switching Frequency: 200-2200kHz; TJmax_C: +125°C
